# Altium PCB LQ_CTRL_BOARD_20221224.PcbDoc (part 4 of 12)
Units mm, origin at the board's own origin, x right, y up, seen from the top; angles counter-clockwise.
Board outline 260 x 142 mm, 6 copper layers (Top Layer, Mid-Layer 1, Mid-Layer 2, Mid-Layer 3, Mid-Layer 4, Bottom Layer); 1105 components, 1039 nets, 3898 pads, 1277 vias.
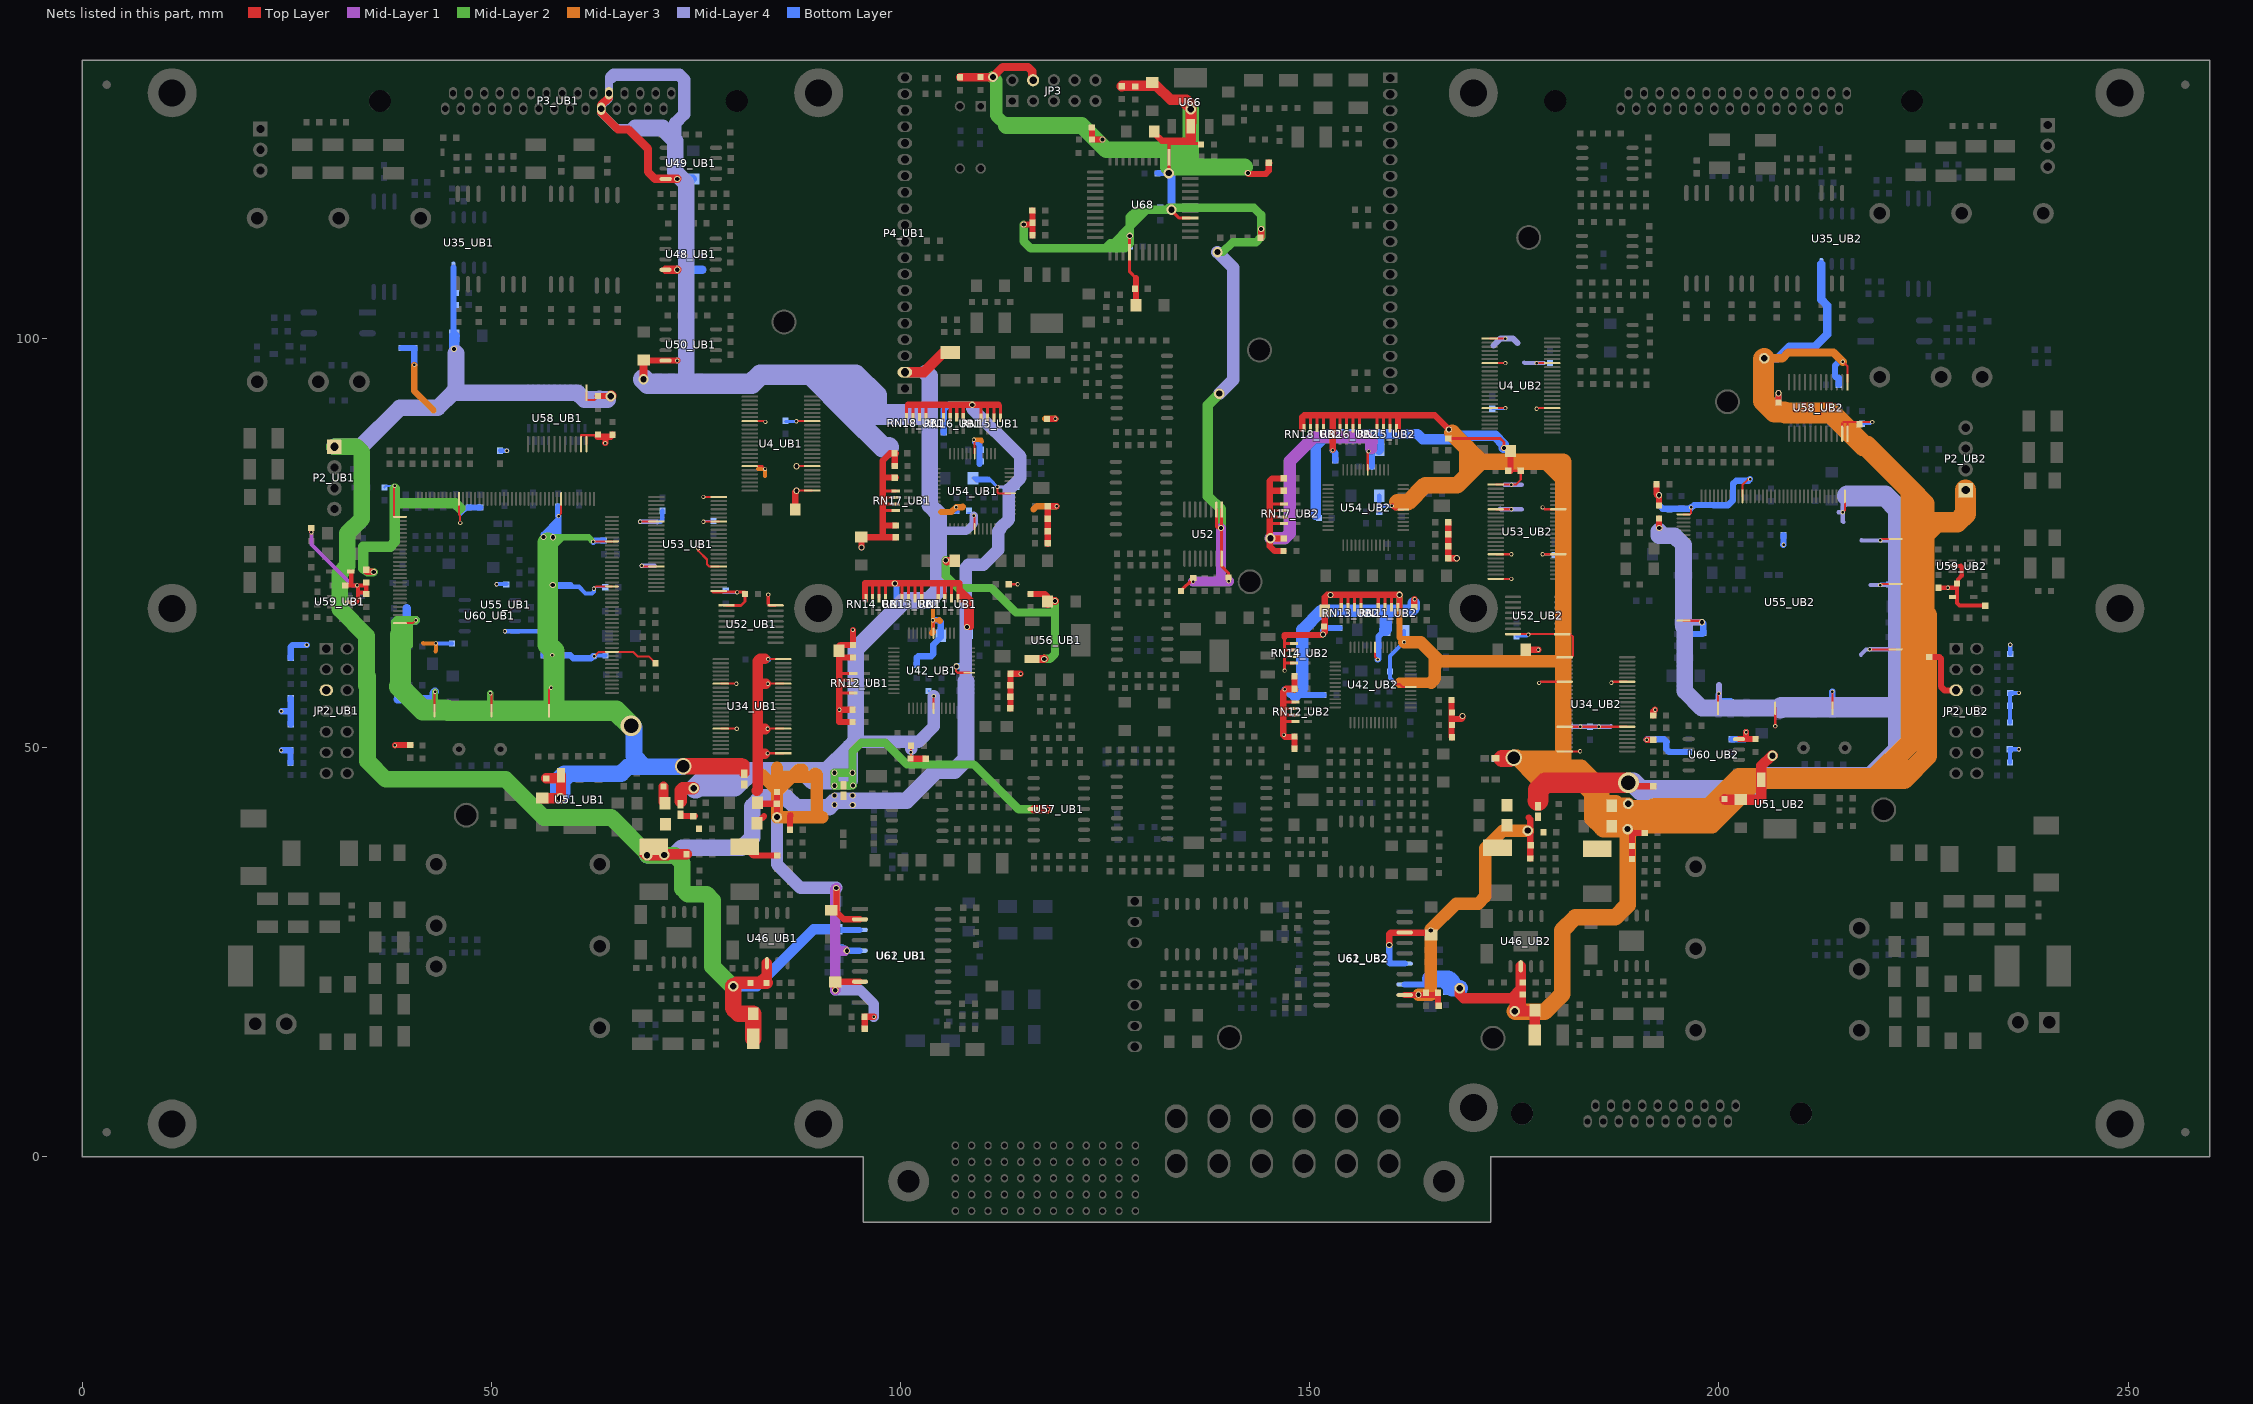
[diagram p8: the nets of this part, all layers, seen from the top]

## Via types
v1: diameter 0.508, hole 0.305, Top Layer to Bottom Layer, 845 vias
v2: diameter 0.762, hole 0.508, Top Layer to Bottom Layer, 317 vias
v3: diameter 1.27, hole 0.762, Top Layer to Bottom Layer, 77 vias
v4: diameter 2.032, hole 1.524, Top Layer to Bottom Layer, 15 vias
v5: diameter 2.032, hole 1.27, Top Layer to Bottom Layer, 11 vias
v6: diameter 1.27, hole 0.711, Top Layer to Bottom Layer, 8 vias
v7: diameter 2.54, hole 1.778, Top Layer to Bottom Layer, 3 vias
v8: diameter 1.524, hole 1.016, Top Layer to Bottom Layer, 1 vias

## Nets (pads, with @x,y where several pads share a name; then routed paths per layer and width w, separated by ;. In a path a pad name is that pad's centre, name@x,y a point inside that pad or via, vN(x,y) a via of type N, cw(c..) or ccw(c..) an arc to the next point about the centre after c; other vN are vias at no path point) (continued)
+3.3V_UB1: C291_UB1.1 C292_UB1.1 C293_UB1.1 C309_UB1.1 C315_UB1.1 C316_UB1.1 C317_UB1.1 C318_UB1.1 C323_UB1.2 C383_UB1.1 C385_UB1.1 C386_UB1.1 C387_UB1.1 C388_UB1.1 C391_UB1.2 C413_UB1.1 C414_UB1.1 C417_UB1.1 C418_UB1.1 C419_UB1.1 D23_UB1.1 L4_UB1.1 R230_UB1.2 R244_UB1.1 R259_UB1.1 R261_UB1.2 R269_UB1.2 R278_UB1.2 R279_UB1.2 R280_UB1.2 R281_UB1.2 R284_UB1.2 R287_UB1.2 R290_UB1.2 R293_UB1.2 R308_UB1.1 R313_UB1.2 R314_UB1.2 R318_UB1.2 R320_UB1.2 R321_UB1.2 R323_UB1.2 R324_UB1.2 R326_UB1.2 R327_UB1.2 R329_UB1.2 RN12_UB1.2 RN12_UB1.4 RN12_UB1.6 RN12_UB1.8 RN17_UB1.2 RN17_UB1.4 RN17_UB1.6 RN17_UB1.8 U4_UB1.1 U4_UB1.7 U4_UB1.18 U4_UB1.31 U4_UB1.42 U34_UB1.1 U34_UB1.7 U34_UB1.18 U34_UB1.24 U34_UB1.31 U34_UB1.42 U42_UB1.18 U52_UB1.1 U52_UB1.16 U53_UB1.1 U53_UB1.7 U53_UB1.18 U53_UB1.24 U53_UB1.31 U53_UB1.42 U54_UB1.18 U61_UB1.6 U62_UB1.2 U62_UB1.8 | length 262.3
  Top Layer w0.254: v1@68.123,77.622 U53_UB1.31@70.028,77.622 ; v1@68.377,72.111 68.38,72.113 U53_UB1.42@70.18,72.113 ; v1(75.286,74.346) 75.286,74.041 76.352,72.974 76.352,72.415 76.654,72.113 U53_UB1.7@77.8,72.113 ; v1(75.921,77.597) 75.937,77.613 U53_UB1.18@77.8,77.613 ; v1@75.921,80.613 U53_UB1.24@77.8,80.613 ; U34_UB1.42@78.054,52.301 v1(79.985,52.301) ; U34_UB1.31@78.054,57.801 79.943,57.801 v1(79.959,57.785) ; U4_UB1.42@81.585,84.382 83.131,84.382 v1(83.464,84.049) ; U4_UB1.31@81.585,89.882 v1@83.49,89.882 ; v1(83.769,49.276) 83.795,49.301 U34_UB1.1@85.674,49.301 ; v1(83.769,52.301) U34_UB1.7@85.674,52.301 ; v1(83.795,57.801) U34_UB1.18@85.674,57.801 ; v1(83.82,60.801) U34_UB1.24@85.674,60.801 ; v1(87.274,89.865) 87.291,89.882 U4_UB1.18@89.205,89.882 ; v2@87.293,81.381 v2(87.3,81.381) ; v2@87.293,81.382 U4_UB1.1@89.205,81.382 ; v2(87.3,84.379) 87.303,84.382 U4_UB1.7@89.205,84.382 ; v1(103.962,65.546) 104.049,65.459 U42_UB1.18@104.049,63.985 ; v1(108.966,87.605) 109.063,87.507 U54_UB1.18@109.063,85.91 ; R293_UB1.2@113.222,69.952 v1(114.3,69.952)
  Top Layer w0.381: U53_UB1.1@77.089,68.986 81.001,68.986 81.001,67.843 80.518,67.361 U52_UB1.1@78.74,67.361 ; v1(83.845,68.682) 83.845,67.539 84.023,67.361 U52_UB1.16@84.74,67.361 ; 92.532,55.626 92.564,55.594 ; 92.532,56.337 92.589,56.394 ; 92.532,57.226 92.564,57.194 ; 92.532,57.996 92.533,57.995 ; 92.558,58.268 RN12_UB1.6@94.247,58.268 ; 92.575,57.461 RN12_UB1.4@94.234,57.461 ; 92.575,59.061 RN12_UB1.8@94.234,59.061 ; 92.6,56.661 RN12_UB1.2@94.234,56.661 ; 97.841,79.019 97.898,78.962 RN17_UB1.2@99.441,78.962 ; 97.841,79.781 97.86,79.762 RN17_UB1.4@99.441,79.762 ; 97.841,80.493 97.911,80.562 RN17_UB1.6@99.441,80.562 ; 97.841,81.318 97.885,81.363 RN17_UB1.8@99.441,81.363
  Top Layer w0.762: L4_UB1.1@80.975,37.871 82.042,36.805 R269_UB1.2@84.938,36.805 ; C291_UB1.1@83.109,41.377 83.337,41.605 ; C292_UB1.1@83.185,43.104 83.21,43.129 C317_UB1.1@84.887,43.129 ; v3@84.836,41.478 84.912,41.554 D23_UB1.1@84.912,44.577 ; C293_UB1.1@86.487,39.954 86.487,41.656 86.563,41.732 ; C383_UB1.1@87.147,79.087 87.147,81.236 v2@87.293,81.381 ; v2(92.024,20.345) C417_UB1.1@92.024,21.361 92.05,21.387 U62_UB1.8@95.052,21.387 ; v2@92.177,32.741 92.177,29.921 93.091,29.007 U62_UB1.2@95.052,29.007 ; 92.532,53.111 92.532,55.626 92.532,56.337 92.532,57.226 92.532,57.996 92.532,60.935 ; v1(92.543,54.61) R281_UB1.2@94.132,54.61 ; 92.645,53.111 R280_UB1.2@94.132,53.111 ; v1(94.183,64.364) 94.209,64.338 94.209,64.313 94.198,64.302 R279_UB1.2@94.198,62.535 92.659,62.535 92.532,62.408 92.532,60.935 ; R278_UB1.2@94.198,61.011 92.608,61.011 92.532,60.935 ; v2(95.225,74.447) C385_UB1.1@95.225,75.743 95.275,75.692 97.841,75.692 ; C418_UB1.1@95.631,15.646 95.631,17.069 C419_UB1.1@95.606,17.094 v1(96.749,17.094) ; R320_UB1.2@99.289,84.404 99.289,85.827 C318_UB1.1@99.416,85.954 ; R321_UB1.2@99.416,75.692 97.841,75.692 ; R323_UB1.2@99.416,77.14 97.853,77.14 97.841,77.152 ; R318_UB1.2@99.441,82.982 97.866,82.982 97.841,83.007 ; C318_UB1.1@99.441,85.928 C318_UB1.1@99.416,85.954 ; R284_UB1.2@113.426,54.813 113.436,54.824 R244_UB1.1@113.436,59.004 v1(114.681,59.004) ; R329_UB1.2@117.907,90.145 118.923,90.145 v1(118.923,90.17) ; R324_UB1.2@118.008,74.91 R326_UB1.2@118.008,76.434 R327_UB1.2@118.008,77.958 R308_UB1.1@118.008,79.477 v1(119.075,79.477) ; 97.841,75.692 97.841,77.152 ; 97.841,77.152 97.841,79.019 97.841,79.781 97.841,80.493 97.841,81.318 97.841,83.007 ; 97.841,83.007 97.841,85.065 98.73,85.954 C318_UB1.1@99.416,85.954
  Top Layer w1.27: 82.448,44.729 82.55,44.831 82.55,49.276 ; 83.439,49.225 82.601,49.225 82.55,49.276 ; 83.439,52.273 83.464,52.248 82.626,52.248 82.55,52.324 ; 83.439,60.858 82.829,60.858 82.55,60.579 82.55,57.81 ; 83.515,57.801 82.559,57.801 82.55,57.81 ; 82.55,49.276 82.55,52.324 ; 82.55,52.324 82.55,57.81
  Mid-Layer 1 w1.27: v2(92.024,20.345) 92.024,32.715 v2(92.151,32.842) ; 92.024,25.044 92.151,25.171 v2@93.193,25.171
  Mid-Layer 2 w0.254: v1(68.174,77.597) v1@68.224,77.648
  Mid-Layer 3 w0.508: 82.575,84.049 v1(83.464,84.049) 83.464,83.185 ; 103.962,64.135 v1(103.962,65.546) ; 103.962,66.878 v1(103.962,65.546) ; 104.736,65.546 v1(103.962,65.546) ; v1(108.966,87.605) 109.88,87.605 ; 109.931,87.376 109.957,87.401
  Mid-Layer 3 w0.762: 103.886,64.033 103.861,64.033 103.962,64.135 ; 104.736,65.546 104.826,65.456 ; 104.978,78.791 106.217,78.791 v1(106.801,79.374) 107.568,79.374 107.62,79.426 ; 116.256,79.121 116.611,79.477 v1(119.075,79.477) ; 117.704,90.17 v1(118.923,90.17)
  Mid-Layer 3 w1.524: 82.931,46.761 84.912,44.78 ; 84.912,47.523 84.912,46.406 ; 87.986,47.295 87.605,47.295 86.716,46.406 ; 90.418,41.455 90.37,41.504 89.535,41.504 ; 84.912,44.602 86.716,46.406 ; 84.912,44.602 84.912,44.78 ; 84.912,44.602 v3(84.912,41.504) 89.535,41.504 ; 84.912,44.78 84.912,46.406 ; 84.912,46.406 86.716,46.406 ; 86.716,46.406 89.205,46.406 89.611,46.812 89.764,46.66 89.764,41.732 89.535,41.504
  Mid-Layer 4 w0.508: v1(68.174,77.597) 70.216,77.597 70.282,77.531 ; v1(68.377,72.212) 69.952,72.212 70.002,72.161
  Mid-Layer 4 w1.27: v2(92.024,20.345) 95.072,20.345 96.749,18.669 v1(96.749,17.094)
  Mid-Layer 4 w1.524: v3(84.912,41.504) 84.912,35.712 87.782,32.842 v2(92.151,32.842)
  Bottom Layer w0.254: v1(68.174,77.597) v1@68.224,77.648 ; v1(75.921,77.597) 75.997,77.673 C387_UB1.1@77.165,77.673
  Bottom Layer w0.381: C316_UB1.1@78.664,69.164 78.664,69.012 78.715,68.961 v1(80.035,68.961) ; C386_UB1.1@85.954,89.84 87.249,89.84 v1(87.274,89.865)
  Bottom Layer w0.508: v1(68.174,77.597) 70.714,77.597 70.891,77.775 70.891,78.918 R313_UB1.2@70.917,78.943
  Bottom Layer w0.762: C388_UB1.1@82.652,60.757 83.775,60.757 v1(83.82,60.801) ; C414_UB1.1@92.685,25.578 92.735,25.527 92.964,25.527 93.32,25.171 U61_UB1.6@95.001,25.171 ; R261_UB1.2@101.981,60.071 101.981,60.985 102.159,61.163 103.759,61.163 104.013,61.417 104.013,62.56 104.927,63.475 C315_UB1.1@104.927,63.652 104.927,65.354 104.724,65.557 104.216,65.557 ; R314_UB1.2@106.858,78.918 v1@106.858,79.299 ; 109.093,87.376 109.322,87.376 109.652,87.046 C391_UB1.2@109.652,84.658
  other v1: 75.921,80.62 83.49,89.789
  other v2: 93.447,25.171
+3.3V_UB2: C291_UB2.1 C292_UB2.1 C293_UB2.1 C309_UB2.1 C315_UB2.1 C316_UB2.1 C317_UB2.1 C318_UB2.1 C323_UB2.2 C383_UB2.1 C385_UB2.1 C386_UB2.1 C387_UB2.1 C388_UB2.1 C391_UB2.2 C413_UB2.1 C414_UB2.1 C417_UB2.1 C418_UB2.1 C419_UB2.1 D23_UB2.1 L4_UB2.1 R230_UB2.2 R244_UB2.1 R259_UB2.1 R261_UB2.2 R269_UB2.2 R278_UB2.2 R279_UB2.2 R280_UB2.2 R281_UB2.2 R284_UB2.2 R287_UB2.2 R290_UB2.2 R293_UB2.2 R308_UB2.1 R313_UB2.2 R314_UB2.2 R318_UB2.2 R320_UB2.2 R321_UB2.2 R323_UB2.2 R324_UB2.2 R326_UB2.2 R327_UB2.2 R329_UB2.2 RN12_UB2.2 RN12_UB2.4 RN12_UB2.6 RN12_UB2.8 RN17_UB2.2 RN17_UB2.4 RN17_UB2.6 RN17_UB2.8 U4_UB2.1 U4_UB2.7 U4_UB2.18 U4_UB2.31 U4_UB2.42 U34_UB2.1 U34_UB2.7 U34_UB2.18 U34_UB2.24 U34_UB2.31 U34_UB2.42 U42_UB2.18 U52_UB2.1 U52_UB2.16 U53_UB2.1 U53_UB2.7 U53_UB2.18 U53_UB2.24 U53_UB2.31 U53_UB2.42 U54_UB2.18 U61_UB2.6 U62_UB2.2 U62_UB2.8 | length 299.5
  Top Layer w0.254: U54_UB2.18@157.092,83.923 157.092,85.997 157.302,86.207 157.226,86.207 v1(157.201,86.182) ; U42_UB2.18@157.984,62.25 157.984,61.091 v1(158.318,60.757) ; U4_UB2.18@172.009,91.474 v1(173.914,91.474) ; U4_UB2.7@172.009,96.974 173.911,96.974 v1(173.914,96.977) ; U4_UB2.1@172.009,99.974 v1(173.914,99.974) ; U53_UB2.24@172.745,70.618 v1@174.644,70.618 ; U53_UB2.18@172.745,73.618 174.641,73.618 v1(174.65,73.609) ; U53_UB2.7@172.745,79.118 174.648,79.118 v1(174.65,79.121) ; U53_UB2.1@172.745,82.118 v1(174.65,82.118) 175.184,82.118 175.793,82.728 R313_UB2.2@175.793,83.82 174.523,83.82 C318_UB2.1@174.269,83.82 ; v1(174.65,70.612) v1@174.644,70.618 ; v1@174.65,70.618 v1@174.644,70.618 ; U52_UB2.16@174.848,63.856 U52_UB2.1@180.848,63.856 181.839,63.856 182.194,63.5 182.194,61.239 181.991,61.036 U34_UB2.1@181.178,61.036 ; v1@177.724,91.474 U4_UB2.31@179.629,91.474 ; v1(177.724,96.977) 177.727,96.974 U4_UB2.42@179.629,96.974 ; v1(178.029,57.887) 178.178,58.036 U34_UB2.7@181.178,58.036 ; v1(178.46,73.613) 178.465,73.618 U53_UB2.31@180.365,73.618 ; v1(178.46,79.35) 178.692,79.118 U53_UB2.42@180.365,79.118 ; U34_UB2.24@181.178,49.536 183.013,49.536 v1(183.032,49.555) ; U34_UB2.18@181.178,52.536 v1(183.083,52.536) v1(185.344,52.536) U34_UB2.31@188.798,52.536 ; v1(186.868,57.912) 186.868,57.861 187.043,58.036 U34_UB2.42@188.798,58.036
  Top Layer w0.381: 145.11,77.317 145.155,77.362 RN17_UB2.2@146.852,77.362 ; 145.11,78.384 145.332,78.162 RN17_UB2.4@146.852,78.162 ; 145.11,78.994 145.142,78.962 RN17_UB2.6@146.852,78.962 ; 145.11,79.73 145.142,79.762 RN17_UB2.8@146.852,79.762 ; 146.761,53.213 146.793,53.181 RN12_UB2.2@148.26,53.181 ; 146.761,54.102 146.882,53.981 RN12_UB2.4@148.26,53.981 ; 146.761,54.737 146.806,54.781 RN12_UB2.6@148.26,54.781 ; 146.761,55.575 146.768,55.582 RN12_UB2.8@148.26,55.582 ; R329_UB2.2@166.929,87.757 173.304,87.757 173.736,87.325 v2(173.736,86.614)
  Top Layer w0.762: R321_UB2.2@146.801,74.02 145.69,74.02 145.11,74.599 v3@145.11,75.59 ; R323_UB2.2@146.827,75.539 145.161,75.539 v3@145.11,75.59 ; R318_UB2.2@146.827,81.381 145.237,81.381 145.11,81.508 ; R320_UB2.2@146.827,82.905 146.801,82.88 145.415,82.88 145.11,82.575 145.11,81.508 ; R279_UB2.2@148.133,58.699 R278_UB2.2@148.133,57.175 147.117,57.175 146.761,56.82 146.761,55.575 146.761,54.737 146.761,54.102 146.761,53.213 146.761,51.537 147.015,51.283 148.082,51.283 R281_UB2.2@148.158,51.359 R280_UB2.2@148.158,49.86 ; v2(159.715,25.883) 159.715,27.229 159.868,27.381 U62_UB2.8@161.615,27.381 164.53,27.381 C417_UB2.1@164.835,27.076 ; U62_UB2.2@161.615,19.761 165.393,19.761 C419_UB2.1@165.673,20.041 165.673,18.542 C414_UB2.1@165.774,18.44 ; R293_UB2.2@162.789,67.183 162.789,68.097 v1(162.814,68.123) ; R308_UB2.1@166.929,77.52 R327_UB2.2@166.929,76.073 R326_UB2.2@166.929,74.599 R324_UB2.2@166.929,73.126 v2(167.97,73.127) ; R244_UB2.1@167.335,55.796 167.335,53.492 ; R284_UB2.2@167.386,51.253 167.335,51.304 167.335,53.492 ; v2@168.656,53.797 168.656,53.619 168.529,53.492 167.335,53.492 ; v2@173.711,86.589 v2(173.736,86.614) 174.32,86.614 174.32,86.462 C309_UB2.1@174.549,86.233 174.549,83.845 C318_UB2.1@174.523,83.82 ; C383_UB2.1@176.403,61.951 v1(177.952,61.951) ; 176.759,41.453 176.962,41.25 C293_UB2.1@176.962,36.449 ; v3@145.11,75.59 145.11,77.317 145.11,78.384 145.11,78.994 145.11,79.73 145.11,81.508
  Mid-Layer 1 w1.524: v3(145.212,75.565) 146.939,75.565 147.549,76.175 147.549,84.963 150.495,87.909 157.023,87.909 157.556,87.376 157.531,87.351 157.531,86.538
  Mid-Layer 3 w0.254: v1(177.724,96.977) 178.867,96.977 178.892,96.952
  Mid-Layer 3 w0.762: v1@147.066,57.099 148.107,57.099 ; 148.158,57.048 148.107,57.099 ; 148.234,57.099 148.107,57.099
  Mid-Layer 3 w1.524: v2(163.297,19.787) 163.322,19.812 164.795,19.812 ; 164.821,19.787 164.795,19.812 ; v3(176.657,39.853) 173.609,39.853 171.45,37.694 171.45,31.775 170.612,30.937 167.919,30.937 164.795,27.813 v2(164.795,27.635) 164.795,19.812
  Mid-Layer 4 w0.508: 173.279,79.197 173.355,79.121 v1(174.65,79.121) 175.87,79.121 175.92,79.07 ; 173.787,82.093 173.812,82.118 v1(174.65,82.118) 175.92,82.118 ; 176.225,97.028 176.276,96.977 v1(177.724,96.977) 178.613,96.977 ; 181.585,52.476 181.644,52.536 v1(183.083,52.536) v1(185.344,52.536) 186.75,52.536 186.817,52.603
  Mid-Layer 4 w0.762: 172.466,99.136 173.304,99.974 v1(173.914,99.974) 174.854,99.974 175.387,99.441
  Bottom Layer w0.254: C387_UB2.1@172.314,91.389 173.829,91.389 v1(173.914,91.474) ; R230_UB2.2@175.285,63.602 176.53,63.602 v1(176.733,63.805) ; v1(177.724,96.977) C316_UB2.1@179.375,96.977 ; v1(178.46,73.613) 179.853,73.613 C388_UB2.1@179.934,73.533 ; C386_UB2.1@181.813,52.578 C386_UB2.1@181.855,52.536
  Bottom Layer w0.508: C386_UB2.1@181.855,52.536 v1(183.083,52.536) v1(185.344,52.536)
  Bottom Layer w0.762: 149.098,57.277 148.92,57.099 v1(146.939,57.099) 147.625,56.413 148.234,56.413 R261_UB2.2@151.689,56.413 ; C391_UB2.2@157.607,84.353 157.607,86.182 157.556,86.233 157.709,86.385 C385_UB2.1@158.471,86.385 ; v1(158.318,60.757) 158.394,60.833 C317_UB2.1@158.394,62.459 158.394,63.551 C315_UB2.1@159.233,64.389 ; v2@159.715,25.832 159.715,23.724 159.842,23.597 U61_UB2.6@161.609,23.597
  Bottom Layer w1.27: 150.724,78.461 150.724,86.843 152.197,88.316 157.988,88.316 ; C385_UB2.1@158.471,86.385 158.471,87.833 157.988,88.316 ; 172.187,88.113 172.161,88.087 ; v2(173.736,86.614) 173.736,87.02 172.669,88.087 172.161,88.087 ; 157.988,88.316 163.144,88.316 163.805,87.655 167.51,87.655 167.942,88.087 172.161,88.087
  Bottom Layer w1.524: 148.234,56.413 148.92,57.099 ; 149.098,57.277 149.098,64.364 151.46,66.726 152.146,66.726 ; 151.689,66.269 152.146,66.726 ; C315_UB2.1@159.233,64.389 159.283,64.44 159.283,66.319 158.877,66.726 ; 162.738,67.615 162.738,67.056 162.408,66.726 158.877,66.726 ; 152.146,66.726 158.877,66.726
  other v1: 146.85,51.537 177.724,91.389
  other v2: 168.681,53.848
+3.3VD_UB1: C313_UB1.1 C320_UB1.1 C346_UB1.2 C347_UB1.2 C348_UB1.2 C349_UB1.2 C350_UB1.2 C351_UB1.2 C352_UB1.2 C353_UB1.2 C406_UB1.1 C408_UB1.2 D24_UB1.2 JP2_UB1.5 LED5_UB1.1 LED13_UB1.1 R15_UB1.1 R257_UB1.2 R258_UB1.2 R259_UB1.2 R277_UB1.1 R303_UB1.1 R306_UB1.1 R307_UB1.1 R309_UB1.1 R311_UB1.2 R312_UB1.1 R331_UB1.1 R336_UB1.1 R346_UB1.2 R352_UB1.1 R353_UB1.1 R358_UB1.2 R361_UB1.2 R362_UB1.2 R363_UB1.2 U51_UB1.3 U55_UB1.9 U55_UB1.71 U55_UB1.93 U55_UB1.107 U55_UB1.121 U55_UB1.143 U55_UB1.159 U55_UB1.170 U58_UB1.23 U58_UB1.24 U59_UB1.5 U60_UB1.8 | length 243.6
  Top Layer w0.254: U55_UB1.71@38.84,65.191 40.426,65.191 v1(40.792,65.557) ; U55_UB1.93@43.04,54.491 43.04,56.553 43.129,56.642 v1(43.129,56.82) ; v1(49.886,56.642) 49.886,56.691 50.04,56.536 U55_UB1.107@50.04,54.491 ; U55_UB1.121@57.04,54.491 57.04,55.982 ; v1(57.302,57.302) 57.048,57.048 57.048,56.312 ; v1(58.217,78.283) 58.54,78.606 U55_UB1.9@58.54,80.391 ; U58_UB1.23@60.976,87.07 60.976,88.154 62.849,88.154 R352_UB1.1@62.885,88.118 ; U58_UB1.24@61.626,87.07 61.626,88.118 R352_UB1.1@62.885,88.118 ; v1(62.459,75.159) 62.491,75.191 U55_UB1.170@64.74,75.191 ; v1(62.535,69.405) 62.821,69.691 U55_UB1.159@64.74,69.691 ; v1(62.611,61.163) 63.139,61.691 U55_UB1.143@64.74,61.691 67.316,61.691 67.869,61.138 69.239,61.138 R331_UB1.1@70.077,60.3 ; R352_UB1.1@63.017,87.986 R352_UB1.1@62.885,88.118 ; 57.04,55.982 57.04,56.304 57.048,56.312 ; 57.04,55.982 57.048,55.99 57.048,56.312
  Top Layer w0.508: LED5_UB1.1@27.991,76.81 27.991,76.327 v1(28.016,76.302) ; R353_UB1.1@32.163,69.787 33.617,69.787 33.731,69.672 33.731,69.051 ; U59_UB1.5@32.62,67.803 33.564,67.803 33.731,67.97 33.731,69.051 ; 32.893,69.875 D24_UB1.2@32.893,71.526 ; v1(33.61,69.799) 34.366,69.799 R277_UB1.1@34.722,70.155 R346_UB1.2@34.722,68.961 ; R346_UB1.2@34.722,68.758 R346_UB1.2@34.722,68.961 ; 33.731,69.051 33.821,68.961 R346_UB1.2@34.722,68.961
  Top Layer w0.762: v1(38.227,50.267) 38.278,50.317 LED13_UB1.1@40.107,50.317 ; R352_UB1.1@62.992,87.96 63.017,87.986 63.957,87.986 ; v1(63.932,87.198) 63.957,87.224 63.957,87.986 ; C406_UB1.1@64.821,88.214 64.592,87.986 63.957,87.986
  Top Layer w1.27: C313_UB1.1@56.21,43.815 v3(58.42,43.815) 58.522,43.917 U51_UB1.3@58.522,46.609 58.141,46.228 C320_UB1.1@56.718,46.228 ; R259_UB1.2@80.899,46.939 80.899,47.981
  Top Layer w2.032: v4(73.457,47.701) 80.518,47.701
  Mid-Layer 1 w0.508: v1(28.016,76.302) 28.016,74.828 33.045,69.799 v1(33.61,69.799)
  Mid-Layer 2 w0.762: 38.278,64.668 39.751,64.668 ; v1(43.129,56.82) 43.129,54.762 43.307,54.585 ; 49.835,54.483 49.886,54.534 v1(49.886,56.642) ; 56.896,73.304 56.896,73.838 58.75,75.692 ; v2(57.531,75.692) 58.75,75.692 ; 62.255,75.336 61.9,75.692 58.75,75.692
  Mid-Layer 2 w1.016: 38.913,61.519 39.903,62.509 39.903,65.557 ; 38.913,63.779 38.278,64.414 38.278,64.668 38.278,65.38 38.456,65.557 39.903,65.557 ; v1(40.792,65.557) 39.903,65.557
  Mid-Layer 2 w2.54: 38.76,57.455 41.631,54.585 43.307,54.585 44.607,54.585 44.708,54.483 49.835,54.483 57.658,54.483 ; 38.913,57.556 38.913,61.519 38.913,63.779 ; 56.896,73.304 56.896,62.56 57.658,61.798 57.658,54.483 ; 56.896,73.838 56.896,75.006 ; v7(67.081,52.654) 65.253,54.483 57.658,54.483
  Mid-Layer 3 w0.508: 41.681,62.763 41.732,62.713 v1(43.231,62.713) 43.231,61.824 43.18,61.773
  Mid-Layer 3 w0.762: v1(40.6,96.749) 40.6,93.563 42.951,91.211
  Bottom Layer w0.254: v1(62.535,69.405) 62.726,69.596 C351_UB1.2@64.008,69.596
  Bottom Layer w0.508: v1(43.231,62.713) R362_UB1.2@45.187,62.713 ; C347_UB1.2@49.886,55.372 v1(49.886,56.642) ; v1(50.648,69.952) 50.698,70.002 R361_UB1.2@51.841,70.002 ; R336_UB1.1@51.054,86.258 v1@51.968,86.258 ; v1(51.664,64.211) U60_UB1.8@52.908,64.211 56.21,64.211 56.413,64.414 R358_UB1.2@56.413,65.659 ; v2(57.506,69.875) 57.734,69.647 60.706,69.647 61.519,68.834 62.306,68.834 62.535,69.063 v1(62.535,69.405) ; v1(62.611,61.163) 62.687,61.239 C350_UB1.2@63.957,61.239
  Bottom Layer w0.762: v1@24.384,54.432 R307_UB1.1@25.502,54.432 ; v1@24.435,49.657 R312_UB1.1@25.476,49.657 R311_UB1.2@25.476,48.108 ; R309_UB1.1@25.502,52.857 R307_UB1.1@25.502,54.432 ; R306_UB1.1@25.502,56.032 R307_UB1.1@25.502,54.432 ; R303_UB1.1@25.502,60.935 25.502,62.281 25.756,62.535 v1(27.457,62.535) ; R258_UB1.2@39.065,98.831 R257_UB1.2@40.595,98.831 40.595,96.754 v1(40.6,96.749) ; R363_UB1.2@56.388,61.29 v1(57.455,61.29) 59.639,61.29 60.02,60.909 62.188,60.909 62.442,61.163 v1(62.611,61.163) ; v2(57.506,69.875) 59.639,69.875 59.665,69.85 ; C353_UB1.2@58.166,79.426 58.166,78.334 v1(58.217,78.283) 58.217,77.826 ; v1(62.459,75.159) 62.611,75.311 C352_UB1.2@63.729,75.311 ; 57.023,75.692 56.413,75.692 v2(56.388,75.717) 56.388,75.997 58.217,77.826 ; 57.023,75.692 v2(57.531,75.692) 58.115,75.692 58.217,75.794 58.217,76.886 ; 57.023,75.692 58.217,76.886 ; 58.217,76.886 58.217,77.826
  Bottom Layer w1.016: R15_UB1.1@38.532,55.905 41.427,55.905 41.453,55.931 42.951,55.931 42.951,56.642 v1(43.129,56.82) ; C408_UB1.2@39.675,67.031 39.675,65.583 C349_UB1.2@39.649,65.557 v1(40.792,65.557)
  Bottom Layer w2.032: 58.979,46.558 59.233,46.812 65.862,46.812 66.7,47.65 68.732,47.65 ; v7@67.437,52.451 67.437,48.946 68.732,47.65 ; v4(73.457,47.701) 73.406,47.65 68.732,47.65
  Bottom Layer w2.54: v3@58.42,44.399 58.42,45.999 58.979,46.558
  other v1: 24.308,49.657 24.333,54.432 51.892,86.258
+3.3VD_UB2: C313_UB2.1 C320_UB2.1 C346_UB2.2 C347_UB2.2 C348_UB2.2 C349_UB2.2 C350_UB2.2 C351_UB2.2 C352_UB2.2 C353_UB2.2 C406_UB2.1 C408_UB2.2 D24_UB2.2 JP2_UB2.5 LED5_UB2.1 LED13_UB2.1 R15_UB2.1 R257_UB2.2 R258_UB2.2 R259_UB2.2 R277_UB2.1 R303_UB2.1 R306_UB2.1 R307_UB2.1 R309_UB2.1 R311_UB2.2 R312_UB2.1 R331_UB2.1 R336_UB2.1 R346_UB2.2 R352_UB2.1 R353_UB2.1 R358_UB2.2 R361_UB2.2 R362_UB2.2 R363_UB2.2 U51_UB2.3 U55_UB2.9 U55_UB2.71 U55_UB2.93 U55_UB2.107 U55_UB2.121 U55_UB2.143 U55_UB2.159 U55_UB2.170 U58_UB2.23 U58_UB2.24 U59_UB2.5 U60_UB2.8 | length 255.9
  Top Layer w0.254: U55_UB2.71@195.685,65.496 197.474,65.496 197.485,65.507 v2@197.79,65.507 ; U55_UB2.93@199.885,54.796 199.885,56.477 v1(200,56.591) ; v1(206.883,52.629) 206.883,52.479 206.885,52.476 U55_UB2.107@206.885,54.796 ; v1(213.868,56.845) 213.885,56.828 U55_UB2.121@213.885,54.796 ; U58_UB2.23@215.069,88.34 215.069,89.593 215.24,89.764 215.798,89.764 ; v1(215.138,78.74) 215.385,78.987 U55_UB2.9@215.385,80.696 ; U58_UB2.24@215.719,88.34 215.719,89.685 215.798,89.764 ; v1(218.44,61.996) U55_UB2.143@221.585,61.996 ; v1(218.745,89.764) 215.798,89.764 ; v1(219.71,69.85) 219.856,69.996 U55_UB2.159@221.585,69.996 ; v1(219.735,75.311) 219.92,75.496 U55_UB2.170@221.585,75.496
  Top Layer w0.508: R346_UB2.2@226.822,69.52 v1(227.99,69.52) ; v1@228.016,69.52 v1(227.99,69.52) ; D24_UB2.2@228.54,68.402 228.88,68.402 229.108,68.631 ; U59_UB2.5@228.595,72.176 229.555,72.176 229.591,72.212 229.667,72.136 229.667,70.993 229.21,70.536 229.21,70.129 R353_UB2.1@229.108,70.028 229.108,69.52 ; LED5_UB2.1@232.537,67.335 229.413,67.335 229.108,67.64 229.108,68.631 ; v1(227.99,69.52) 229.108,69.52 ; 229.108,68.631 229.108,69.52
  Top Layer w0.762: v7(188.951,45.695) 189.382,45.263 R361_UB2.2@191.973,45.263 ; v1(191.186,50.952) R363_UB2.2@191.989,50.952 ; LED13_UB2.1@191.973,53.899 191.973,54.392 v1(192.197,54.615) ; R277_UB2.1@192.684,77.996 192.684,76.835 v2(192.71,76.81) ; U60_UB2.8@202.459,51.029 203.327,51.029 ; v1(203.327,51.867) 203.327,51.029 ; R358_UB2.2@204.343,51.029 203.327,51.029 ; R258_UB2.2@207.289,92.151 v2(207.289,93.294) ; R331_UB2.1@225.704,61.062 226.924,61.062 227.127,60.858 227.127,57.455 227.609,56.972 228.956,56.972 JP2_UB2.5@228.981,56.998
  Top Layer w1.27: 177.902,43.383 177.902,43.536 177.902,44.78 177.927,44.806 ; C320_UB2.1@200.685,43.713 200.762,43.637 C313_UB2.1@202.692,43.637 204.902,43.637 205.181,43.917 U51_UB2.3@205.181,46.05 205.181,47.752 206.451,49.022 v3@206.578,49.022
  Top Layer w2.54: 177.902,43.536 177.927,43.561 177.927,44.806 178.816,45.695 v7(188.951,45.695)
  Mid-Layer 4 w0.508: 214.62,78.74 v1(215.138,78.74) ; 215.214,77.546 215.138,77.622 v1(215.138,78.74) ; 215.697,80.721 215.138,80.162 v1(215.138,78.74) ; 217.348,61.341 217.348,61.366 217.977,61.996 v1(218.44,61.996) 218.446,62.001 221.945,62.001 ; 217.424,75.336 217.449,75.311 v1(219.735,75.311) 221.894,75.311 221.945,75.26 ; 218.542,69.85 v1(219.71,69.85) 221.92,69.85 221.945,69.875
  Mid-Layer 4 w0.762: 195.834,64.643 196.494,65.303 v2(197.942,65.303) ; 200,57.633 v1(200,56.591) 200,54.864 200.025,54.839 ; v2(207.289,93.294) 207.289,91.897 207.416,91.77
  Mid-Layer 4 w2.032: 192.684,76.429 192.684,75.87 194.589,75.87 195.682,74.778 195.682,64.795 195.834,64.643 195.834,56.896 197.891,54.839 200.025,54.839 207.543,54.839
  Mid-Layer 4 w2.54: v7(188.951,45.695) 189.535,45.695 190.449,44.78 203.911,44.78 205.486,46.355 218.567,46.355 221.945,49.733 221.945,55.016 ; 207.543,54.839 207.62,54.915 221.844,54.915 221.945,55.016 ; 215.697,80.721 220.32,80.721 221.945,79.096 221.945,75.26 221.945,69.875 221.945,62.001 221.945,55.016
  Bottom Layer w0.254: R257_UB2.2@217.5,89.56 218.542,89.56 v1(218.745,89.764)
  Bottom Layer w0.508: v1(215.138,78.74) 215.138,79.321 C406_UB2.1@215.777,79.959 ; v1(219.71,69.85) 219.786,69.926 C349_UB2.2@220.802,69.926 ; v1(219.735,75.311) 220.726,75.311 C348_UB2.2@221.082,75.667 221.056,75.692 C346_UB2.2@221.056,77.14 ; R309_UB2.1@235.56,53.072 R307_UB2.1@235.56,55.118 235.56,56.617 R306_UB2.1@235.61,56.667 v1(236.652,56.667) ; R311_UB2.2@235.585,48.17 235.585,49.733 R312_UB2.1@235.534,49.784 235.548,49.798 v1(236.652,49.798) ; R303_UB2.1@235.59,61.443 235.61,61.463 v1(235.61,62.56)
  Bottom Layer w0.762: v1(191.186,50.952) 191.237,51.003 193.294,51.003 193.624,50.673 193.573,50.622 193.573,49.784 193.904,49.454 R362_UB2.2@196.312,49.454 ; C353_UB2.2@196.469,63.881 197.968,63.881 R15_UB2.1@198.095,64.008 198.095,65.151 v2(197.942,65.303) C352_UB2.2@196.469,65.303 ; v1@200,56.54 199.949,56.49 C351_UB2.2@199.949,55.575 200.025,55.651 C347_UB2.2@201.447,55.651 ; C408_UB2.2@201.574,51.003 203.175,51.003 203.327,51.156 v1(203.327,51.867) ; v1@207.874,74.778 207.899,74.803 R336_UB2.1@207.899,75.946 ; C350_UB2.2@213.843,55.575 213.843,56.82 v1(213.868,56.845)
  other v1: 207.901,74.778
  other v3: 206.553,48.997
+3V3A_UB1: C343_UB1.2 C344_UB1.2 C345_UB1.2 R277_UB1.2 U55_UB1.34 U55_UB1.45 | length 38.4
  Top Layer w0.254: R277_UB1.2@34.722,71.501 R277_UB1.2@34.722,71.73 ; v1(38.176,81.966) 38.125,81.915 38.125,78.257 38.192,78.191 U55_UB1.45@38.84,78.191 ; U55_UB1.34@46.04,80.391 46.04,78.461 46.203,78.298 v1(46.203,77.445)
  Top Layer w0.762: R277_UB1.2@34.722,71.501 34.743,71.48 35.607,71.48 v2(35.636,71.45)
  Mid-Layer 2 w0.254: v1(46.203,77.445) 46.203,79.223
  Mid-Layer 2 w1.016: 34.519,71.755 34.874,71.399 35.585,71.399 v2(35.636,71.45)
  Mid-Layer 2 w1.27: 34.519,71.755 34.366,71.907 34.366,74.549 37.643,74.549 38.227,75.133 38.227,79.832 ; 38.202,81.61 38.227,81.585 38.227,79.832 ; 46.203,79.223 45.593,79.832 38.227,79.832
  Bottom Layer w0.254: C343_UB1.2@36.957,81.788 37.135,81.966 v1(38.176,81.966) ; v1(46.203,77.445) 46.203,78.308 C344_UB1.2@47.219,79.324
  Bottom Layer w0.762: C344_UB1.2@47.219,79.324 C345_UB1.2@48.666,79.324
+3V3A_UB2: C343_UB2.2 C344_UB2.2 C345_UB2.2 R277_UB2.2 U55_UB2.34 U55_UB2.45 | length 22.5
  Top Layer w0.254: U55_UB2.45@195.685,78.496 196.451,78.496 196.596,78.641 v1(196.596,79.35) ; U55_UB2.34@202.885,80.696 202.885,82.108 203.581,82.804 v1(203.81,82.804)
  Top Layer w0.762: C343_UB2.2@192.38,82.169 192.38,80.975 192.684,80.67 R277_UB2.2@192.684,79.571
  Bottom Layer w0.762: v2(192.684,80.823) 192.684,79.604 193.116,79.172 C344_UB2.2@195.428,79.172 v1@196.418,79.172 ; v1(196.596,79.35) v1@196.418,79.172 ; v1(203.81,82.804) 203.606,82.601 202.108,82.601 201.727,82.22 201.727,80.213 201.117,79.604 199.365,79.604 199.339,79.629 196.977,79.629 196.52,79.172 v1@196.418,79.172
+3V3MS: C437.1 C439.1 C449.2 C450.2 C451.2 C452.2 C453.2 C454.2 JP3.4 LED1.1 LED2.1 LED3.1 LED4.1 LED19.1 LED20.1 LED21.1 R5.2 R7.1 R9.1 R35.1 R36.1 R37.1 R38.1 U52.1 U52.2 U52.16 U66.2 U68.15 U68.26 U68.35 | length 244.4
  Top Layer w0.381: v2(128.016,112.522) 128,112.506 U68.15@128,110.52 128,108.122 128.778,107.343 ; v3(132.791,120.193) 132.8,120.201 U68.35@132.8,122.12 132.8,123.825 136.576,123.825 LED21.1@136.728,123.673 ; v3@133.147,115.595 134.022,114.72 U68.26@135.4,114.72 ; R5.2@134.264,69.139 R9.1@135.763,70.637 ; v1(135.763,70.282) R9.1@135.763,70.637 ; R9.1@135.763,70.714 R9.1@135.763,70.637 ; U52.2@138.593,79.087 138.593,77.028 138.786,76.835 v2@139.243,76.835 ; U52.1@139.243,79.087 v2@139.243,76.835 ; v1(140.106,70.307) 140.081,70.333 R7.1@140.081,70.764 140.081,71.313 139.243,72.151 U52.16@139.243,73.087 v2@139.243,76.835
  Top Layer w0.762: v2(115.062,113.894) R37.1@116.078,113.894 ; R38.1@116.103,115.621 116.129,115.595 R37.1@116.129,114.122 R35.1@116.129,112.598 ; R36.1@123.393,125.4 LED20.1@123.393,124.282 124.663,124.282 v2(124.689,124.308) ; C449.2@128.778,104.064 128.778,107.343 ; C452.2@131.013,125.273 131.013,125.07 131.953,124.13 135.306,124.13 135.458,124.282 ; v2(142.443,120.193) 142.545,120.091 144.628,120.091 145.009,120.472 LED1.1@145.009,121.463 LED1.1@145.059,121.412 ; LED2.1@144.069,112.37 v2(144.069,113.36)
  Top Layer w1.016: LED4.1@107.264,131.902 111.227,131.902 112.486,133.162 115.575,133.162 116.098,132.639 116.098,131.647 JP3.4@116.205,131.54
  Top Layer w1.27: LED19.1@127.045,130.81 127.122,130.886 131.275,130.886 133.003,129.159 134.29,129.159 ; C437.1@130.404,130.886 C437.1@130.759,131.242 ; 135.458,124.282 U66.2@135.458,125.908 v3@135.458,127.483 ; U66.2@135.509,126.34 v3@135.509,127.533 ; 134.29,129.159 v3(135.458,127.991) v3@135.458,127.483 ; 134.29,129.159 134.95,129.159 135.509,128.6 v3@135.509,127.533 ; v3@135.458,127.483 v3@135.509,127.533
  Mid-Layer 1 w1.27: v1(135.763,70.282) 138.887,70.282 ; v2(139.167,76.81) 139.167,70.561 138.887,70.282 ; v1(140.106,70.307) 140.081,70.282 138.887,70.282
  Mid-Layer 2 w1.016: v2(115.062,113.894) 115.062,111.853 115.917,110.998 125.019,110.998 ; v3(133.121,115.697) v3@132.512,115.697 ; v3(138.735,110.541) 139.37,110.541 140.564,111.735 143.434,111.735 144.069,112.37 v2(144.069,113.36) 144.069,115.087 143.205,115.951 132.766,115.951 v3@132.512,115.697 ; 125.019,110.998 125.628,111.608 126.035,111.608 ; 125.019,110.998 127.432,110.998 128.016,111.582 v2(128.016,112.522) ; 126.035,111.608 127.102,111.608 v2(128.016,112.522) ; 126.035,111.608 128.016,113.589 ; v2(128.016,112.522) 128.016,113.589 ; 128.016,113.589 128.016,113.665 ; 128.016,113.665 130.048,115.697 ; 128.016,113.665 128.016,114.833 128.88,115.697 130.048,115.697 ; 130.048,115.697 v3@132.512,115.697
  Mid-Layer 2 w1.27: v3(138.963,93.243) 137.566,91.846 137.566,80.696 139.167,79.096 v2(139.167,76.81)
  Mid-Layer 2 w1.524: v3(111.303,131.928) 111.684,131.547 111.684,127.254 112.928,126.009
  Mid-Layer 2 w2.032: 112.928,126.009 122.149,126.009 125.12,123.038 132.817,123.038 ; 135.458,121.336 135.458,123.165 ; v3(135.458,127.991) 135.458,123.165 ; 138.811,120.929 134.722,120.929 ; 142.062,120.904 142.037,120.929 134.722,120.929 ; 132.715,122.936 132.817,123.038 ; 132.715,122.936 132.715,120.929 134.722,120.929 ; 132.715,122.936 134.722,120.929 ; 132.817,123.038 135.331,123.038 135.458,123.165
  Mid-Layer 4 w1.524: v3(138.735,110.541) 140.665,108.61 140.665,94.945 v3(138.963,93.243)
  Bottom Layer w0.381: C454.2@128.016,111.227 v2(128.016,112.522) ; C453.2@131.75,116.002 132.817,116.002 v3(133.121,115.697)
  Bottom Layer w0.762: C451.2@131.445,120.193 v3(132.791,120.193)
  Bottom Layer w1.016: v3(132.791,120.193) 133.121,119.863 v3(133.121,115.697)
+5V_UB1: C17_UB1.1 C228_UB1.1 C237_UB1.2 C238_UB1.2 C254_UB1.1 C255_UB1.1 C258_UB1.1 C265_UB1.1 C266_UB1.2 C294_UB1.1 C295_UB1.2 C367_UB1.1 C368_UB1.2 C405_UB1.2 C415_UB1.1 C416_UB1.1 D21_UB1.1 L3_UB1.1 P2_UB1.1 R39_UB1.1 R40_UB1.1 R229_UB1.1 R239_UB1.2 R263_UB1.1 R283_UB1.2 RN11_UB1.1 RN11_UB1.3 RN11_UB1.5 RN11_UB1.7 RN13_UB1.1 RN13_UB1.3 RN13_UB1.5 RN13_UB1.7 RN14_UB1.1 RN14_UB1.3 RN14_UB1.5 RN14_UB1.7 RN15_UB1.1 RN15_UB1.3 RN15_UB1.5 RN15_UB1.7 RN16_UB1.1 RN16_UB1.3 RN16_UB1.5 RN16_UB1.7 RN18_UB1.1 RN18_UB1.3 RN18_UB1.5 RN18_UB1.7 U35_UB1.8 U42_UB1.6 U46_UB1.2 U54_UB1.6 U58_UB1.1 U61_UB1.8 | length 415.3
  Top Layer w0.254: U58_UB1.1@61.626,93.37 61.626,92.527 61.697,92.456 62.56,92.456 C405_UB1.2@63.043,92.939 ; v2@106.782,59.919 106.782,59.305 106.952,59.135 U42_UB1.6@108.399,59.135 ; v1@111.836,81.661 111.836,81.229 112.005,81.06 ; 111.899,81.06 112.005,81.06 ; U54_UB1.6@113.413,81.06 112.005,81.06
  Top Layer w0.381: 96.545,70.079 96.577,70.047 RN14_UB1.5@96.577,68.25 ; 97.333,70.079 97.377,70.034 RN14_UB1.3@97.377,68.25 ; 98.146,70.079 98.177,70.047 RN14_UB1.1@98.177,68.25 ; RN13_UB1.7@100.197,68.25 100.197,70.021 100.254,70.079 ; RN18_UB1.7@100.73,90.399 100.73,91.774 100.838,91.882 100.914,91.882 ; RN13_UB1.5@100.997,68.25 100.997,70.009 101.067,70.079 ; RN18_UB1.5@101.53,90.399 101.53,91.882 ; RN13_UB1.3@101.797,68.25 101.797,69.945 101.93,70.079 ; RN18_UB1.3@102.33,90.399 102.33,91.882 102.33,91.948 ; RN13_UB1.1@102.597,68.25 102.597,70.009 102.667,70.079 ; RN18_UB1.1@103.13,90.399 103.13,91.882 103.13,92.05 ; RN11_UB1.7@104.616,68.25 104.616,69.996 104.699,70.079 ; RN16_UB1.7@105.277,90.348 105.277,91.882 ; 105.308,70.079 105.416,69.971 RN11_UB1.5@105.416,68.25 ; RN16_UB1.5@106.077,90.348 106.077,91.882 ; RN11_UB1.3@106.216,68.25 106.216,69.729 106.566,70.079 ; RN16_UB1.3@106.877,90.348 106.877,91.882 ; RN16_UB1.1@107.677,90.348 107.677,91.882 ; RN15_UB1.7@109.823,90.297 109.823,91.882 ; RN15_UB1.5@110.623,90.297 110.623,91.882 ; RN15_UB1.3@111.423,90.297 111.423,91.882 ; RN15_UB1.1@112.224,90.297 112.224,91.865
  Top Layer w0.762: C405_UB1.2@63.017,92.939 C405_UB1.2@63.043,92.939 v3@64.033,92.939 ; R229_UB1.1@73.279,41.783 73.431,41.631 D21_UB1.1@74.905,41.631 ; RN14_UB1.7@95.656,68.097 95.656,70.079 96.545,70.079 97.333,70.079 98.146,70.079 100.254,70.079 101.067,70.079 101.93,70.079 102.667,70.079 104.699,70.079 105.308,70.079 106.566,70.079 ; 100.914,91.882 101.53,91.882 102.33,91.882 103.13,91.882 105.277,91.882 106.077,91.882 106.877,91.882 107.677,91.882 109.823,91.882 110.623,91.882 111.423,91.882 111.989,91.882 ; 106.642,70.079 107.188,70.079 107.213,70.053 107.213,69.367 ; 107.213,69.367 108.585,67.996 108.585,64.719 v2(108.128,64.719) 108.153,64.745 108.153,68.123 107.213,68.123 107.213,69.367
  Top Layer w1.27: v3(64.592,92.913) v3@64.668,92.989 ; L3_UB1.1@68.732,36.957 L3_UB1.1@69.164,36.957 ; C416_UB1.1@71.044,45.237 71.044,43.358 C255_UB1.1@71.222,43.18 ; v3@71.603,36.982 v3@71.628,36.957 ; R239_UB1.2@73.863,36.957 v3@71.628,36.957 ; C294_UB1.1@81.94,17.399 81.991,17.45 C17_UB1.1@81.991,14.427 ; 82.702,21.234 83.668,22.2 ; R263_UB1.1@83.668,21.26 83.668,22.2 ; U46_UB1.2@83.668,23.647 83.668,22.2 ; L3_UB1.1@69.164,36.957 v3(69.037,36.83) 71.501,36.83 v3@71.628,36.957 ; L3_UB1.1@69.164,36.957 v3@71.628,36.957
  Top Layer w1.524: v3(79.553,20.828) 79.959,21.234 C295_UB1.2@81.661,21.234 82.702,21.234 R263_UB1.1@83.642,21.234
  Top Layer w2.032: v3(79.553,20.828) 79.553,18.136 80.213,17.475 C294_UB1.1@82.017,17.475 82.017,14.453 C17_UB1.1@81.991,14.427
  Mid-Layer 2 w2.032: P2_UB1.1@30.836,86.766 33.503,86.766 34.188,86.081 34.188,77.953 32.385,76.149 32.385,72.187 31.496,71.298 31.496,66.904 34.747,63.652 34.747,57.556 34.874,57.429 ; 34.925,58.725 34.874,58.674 34.874,57.429 ; v3(69.037,36.83) 72.415,36.83 73.33,35.916 73.33,32.741 73.99,32.08 76.302,32.08 77.038,31.344 77.038,23.241 v3@79.477,20.803 ; v3(71.145,36.881) 69.24,36.881 64.668,41.453 56.413,41.453 51.74,46.126 37.084,46.126 34.874,48.336 34.874,57.429
  Mid-Layer 4 w0.381: v1(111.836,81.839) 112.928,81.839 113.233,81.534
  Mid-Layer 4 w1.524: 108.001,58.115 107.95,58.166 107.95,71.958 108.306,72.314 110.098,72.314 111.919,74.136 111.919,76.41 112.166,76.657 112.166,76.81 113.233,77.876 113.233,81.534 114.656,82.956 114.656,85.547 108.763,91.44
  Mid-Layer 4 w2.032: P2_UB1.1@30.836,86.766 34.086,86.766 38.837,91.516 43.459,91.516 45.288,93.345 ; 45.695,98.146 45.695,93.751 45.288,93.345 ; 63.221,92.634 63.119,92.532 ; v3@64.211,92.532 63.119,92.532 ; v3(69.037,36.83) 72.339,36.83 73.254,37.744 80.62,37.744 81.89,39.014 81.89,42.824 82.982,43.917 86.03,43.917 87.224,42.723 91.288,42.723 92.075,43.51 100.736,43.51 104.419,47.193 106.604,47.193 108.001,48.59 108.001,58.115 ; 45.288,93.345 60.554,93.345 61.366,92.532 63.119,92.532
  Bottom Layer w0.381: C368_UB1.2@114.173,81.864 114.148,81.839 v1(111.836,81.839) 111.595,82.08 111.593,82.08 111.214,82.46 111.214,82.461 111.074,82.601 111.073,82.601 ; 111.073,82.601 109.22,82.601 108.864,82.956 110.717,82.956 111.073,82.601
  Bottom Layer w0.762: U35_UB1.8@45.37,108.636 45.37,100.731 C228_UB1.1@45.796,100.305 ; C415_UB1.1@92.126,27.788 92.202,27.711 U61_UB1.8@95.001,27.711 ; v2(99.314,70.053) 99.517,69.85 R40_UB1.1@99.517,66.345 ; R39_UB1.1@105.283,88.494 105.283,91.262 105.893,91.872 v2(108.763,91.872) ; v2(106.858,59.919) 107.721,59.919 108.102,60.3 108.102,63.881 C265_UB1.1@108.128,63.906 v2(108.128,64.719)
  Bottom Layer w1.27: v2@45.466,98.73 C228_UB1.1@45.466,100.305 ; v3(79.553,20.828) 82.423,20.828 89.383,27.788 C415_UB1.1@92.126,27.788
  other v2: 94.158,42.977 91.923,43.002 91.923,44.145 94.158,44.145 45.456,98.703
+5V_UB2: C17_UB2.1 C228_UB2.1 C237_UB2.2 C238_UB2.2 C254_UB2.1 C255_UB2.1 C258_UB2.1 C265_UB2.1 C266_UB2.2 C294_UB2.1 C295_UB2.2 C367_UB2.1 C368_UB2.2 C405_UB2.2 C415_UB2.1 C416_UB2.1 D21_UB2.1 L3_UB2.1 P2_UB2.1 R39_UB2.1 R40_UB2.1 R229_UB2.1 R239_UB2.2 R263_UB2.1 R283_UB2.2 RN11_UB2.1 RN11_UB2.3 RN11_UB2.5 RN11_UB2.7 RN13_UB2.1 RN13_UB2.3 RN13_UB2.5 RN13_UB2.7 RN14_UB2.1 RN14_UB2.3 RN14_UB2.5 RN14_UB2.7 RN15_UB2.1 RN15_UB2.3 RN15_UB2.5 RN15_UB2.7 RN16_UB2.1 RN16_UB2.3 RN16_UB2.5 RN16_UB2.7 RN18_UB2.1 RN18_UB2.3 RN18_UB2.5 RN18_UB2.7 U35_UB2.8 U42_UB2.6 U46_UB2.2 U54_UB2.6 U58_UB2.1 U61_UB2.8 | length 543
  Top Layer w0.254: v1(160.02,79.527) 160.02,79.657 160.093,79.73 160.093,79.352 160.372,79.073 U54_UB2.6@161.442,79.073 ; v1@160.401,57.734 161.011,57.734 161.345,57.4 U42_UB2.6@162.334,57.4 ; v1(215.138,97.13) 215.163,97.13 215.719,96.574 U58_UB2.1@215.719,94.64
  Top Layer w0.381: v1(146.939,59.4) 146.939,60.451 ; 147.193,63.754 146.939,63.5 146.939,62.713 ; RN14_UB2.7@148.082,60.319 147.071,60.319 146.939,60.451 ; RN14_UB2.5@148.082,61.119 146.958,61.119 146.939,61.138 ; RN14_UB2.3@148.082,61.919 146.971,61.919 146.939,61.951 ; RN14_UB2.1@148.082,62.719 146.945,62.719 146.939,62.713 ; 150.089,90.601 150.095,90.595 RN18_UB2.5@150.095,89.052 ; RN18_UB2.3@150.895,89.052 150.895,90.595 150.901,90.601 ; 151.587,90.601 151.695,90.493 RN18_UB2.1@151.695,89.052 ; 153.518,90.601 153.704,90.415 RN16_UB2.7@153.704,89.027 ; RN13_UB2.7@153.859,67.158 153.859,68.608 153.932,68.682 ; 154.457,90.601 154.504,90.555 RN16_UB2.5@154.504,89.027 ; RN13_UB2.5@154.659,67.158 154.659,68.553 154.788,68.682 ; 155.245,90.601 155.304,90.542 RN16_UB2.3@155.304,89.027 ; RN13_UB2.3@155.459,67.158 155.459,68.515 155.626,68.682 ; 156.032,90.601 156.104,90.53 RN16_UB2.1@156.104,89.027 ; RN13_UB2.1@156.259,67.158 156.259,68.68 156.261,68.682 ; 158.093,90.601 158.064,90.601 158.21,90.455 RN15_UB2.7@158.21,89.027 ; RN11_UB2.7@158.38,67.158 158.38,68.515 158.547,68.682 ; 158.826,90.601 159.01,90.417 RN15_UB2.5@159.01,89.027 ; RN11_UB2.5@159.18,67.158 159.18,68.579 159.283,68.682 ; 159.664,90.601 159.639,90.601 159.81,90.43 RN15_UB2.3@159.81,89.027 ; 159.969,68.682 159.98,68.67 RN11_UB2.3@159.98,67.158 ; 146.939,60.451 146.939,61.138 ; 146.939,61.138 146.939,61.951 ; 146.939,61.951 146.939,62.713
  Top Layer w0.762: 146.939,63.5 146.939,63.754 147.193,63.754 151.486,63.754 151.841,64.11 C265_UB2.1@151.841,66.711 151.841,68.377 152.146,68.682 153.932,68.682 154.788,68.682 155.626,68.682 156.261,68.682 158.547,68.682 159.283,68.682 159.969,68.682 160.781,68.682 v2@160.781,68.68 ; 149.098,88.906 149.098,90.373 149.327,90.601 150.089,90.601 150.901,90.601 151.587,90.601 152.806,90.601 ; v1@152.806,86.382 152.806,90.601 ; 158.064,90.601 156.032,90.601 155.245,90.601 154.457,90.601 153.518,90.601 152.806,90.601 ; 158.093,90.601 158.826,90.601 159.639,90.601 160.579,90.601 ; 159.664,90.601 160.579,90.601 ; 160.807,88.9 160.807,90.373 160.579,90.601 ; RN11_UB2.1@160.96,67.159 v2@160.96,68.682 ; v2(167.005,88.875) 165.278,90.601 160.579,90.601 ; C258_UB2.1@189.382,36.373 R239_UB2.2@189.382,37.973 189.382,39.649 189.484,39.548 D21_UB2.1@190.932,39.548
  Top Layer w1.27: v3(168.351,20.599) 168.351,19.863 168.834,19.38 174.676,19.38 ; v3(175.057,17.78) v3@175.057,17.831 ; U46_UB2.2@175.793,23.266 175.793,20.498 ; C17_UB2.1@177.444,14.63 177.521,14.707 177.521,17.755 176.327,17.755 ; 174.676,19.38 175.793,20.498 ; 174.676,19.38 174.981,19.38 175.057,19.304 v3@175.057,17.831 ; v3@175.057,17.831 175.006,17.78 175.031,17.755 176.327,17.755 ; 175.793,20.498 175.793,18.288 176.327,17.755
  Top Layer w2.032: 173.457,48.666 v4@174.523,48.666
  Mid-Layer 3 w0.762: v2(160.985,68.656) 160.985,63.449 v1(161.544,62.89)
  Mid-Layer 3 w1.016: v3(205.537,97.561) 207.747,97.561 208.458,98.273 213.995,98.273 v1(215.138,97.13)
  Mid-Layer 3 w1.27: 160.985,57.937 164.846,57.937
  Mid-Layer 3 w1.524: v1(161.544,62.89) 163.551,62.89 165.303,61.138 ; 164.846,57.937 165.303,58.395 165.303,59.969 ; 181,60.706 180.848,60.554 165.887,60.554 ; 187.376,43.155 187.401,43.129 v3(188.925,43.129) ; 165.303,59.969 165.303,61.138 ; 165.303,59.969 165.887,60.554 ; 165.303,61.138 165.887,60.554
  Mid-Layer 3 w2.032: 160.731,79.959 162.001,79.959 164.109,82.067 168.046,82.067 169.24,83.261 ; 167.411,88.443 169.24,86.614 ; v4(174.955,48.768) 175.362,48.768 177.775,46.355 182.55,46.355 182.702,46.203 ; v3(175.057,17.78) 175.108,17.729 178.74,17.729 180.848,19.837 180.848,27.661 182.448,29.261 187.35,29.261 188.849,30.759 v3(188.849,40.03) ; v4@175.565,48.616 177.267,48.616 ; 177.927,46.203 182.702,46.203 ; 187.376,43.155 185.623,43.155 ; 187.401,43.129 187.401,40.335 187.706,40.03 ; 188.671,42.291 188.671,40.208 v3(188.849,40.03) ; 192.126,42.545 188.874,42.545 188.824,42.494 188.849,42.469 v3(188.849,40.03) ; 207.315,46.203 204.851,46.203 199.161,40.513 190.119,40.513 189.992,40.64 189.382,40.03 v3(188.849,40.03) ; 169.24,83.261 170.917,84.938 ; 169.24,83.261 169.24,86.614 ; 169.24,86.614 170.917,84.938 ; 170.917,84.938 178.918,84.938 ; 177.267,48.616 178.359,47.523 181,47.523 ; 177.267,48.616 180.746,48.616 181,48.87 ; 178.918,84.938 181,84.938 181,82.855 ; 178.918,84.938 181,82.855 ; 181,47.523 183.159,47.523 184.556,46.126 ; 181,47.523 181,48.87 ; 181,48.87 181,60.706 181,82.855 ; 182.702,46.203 184.556,44.348 ; 184.556,44.221 185.623,43.155 ; 184.556,44.221 184.556,41.326 185.623,40.259 ; 184.556,44.221 184.556,44.348 ; 184.556,44.348 184.556,46.126 ; 184.556,46.126 185.623,45.06 185.623,43.155 ; 185.623,40.259 185.852,40.03 187.706,40.03 ; 185.623,40.259 185.623,43.155 ; 187.706,40.03 v3(188.849,40.03)
  Mid-Layer 3 w2.54: 192.126,42.545 198.831,42.545 202.489,46.203 204.851,46.203 219.024,46.203 ; v3(205.537,97.561) 205.435,97.46 205.435,92.329 206.781,90.983 208.005,90.983 208.106,90.881 213.686,90.881 217.725,86.843 218.034,86.843 223.469,81.407 ; P2_UB2.1@230.149,81.458 230.149,78.537 229.133,77.521 226.619,77.521 225.095,75.997 ; 219.024,46.203 222.606,46.203 225.4,48.997 225.4,66.14 225.095,66.445 225.095,75.997 ; 219.024,46.203 223.469,50.648 223.469,81.407 ; 223.469,81.407 225.095,79.781 225.095,75.997
  Bottom Layer w0.508: C238_UB2.2@158.496,78.816 158.496,79.502 ; C228_UB2.1@158.496,80.772 158.496,79.502 ; v1(160.401,57.887) 159.817,58.471 C237_UB2.2@159.817,59.284 159.817,61.163 v1(161.544,62.89) C367_UB2.1@161.544,64.237 ; C405_UB2.2@161.239,79.737 160.23,79.737 v1(160.02,79.527) 159.995,79.502 158.496,79.502
  Bottom Layer w0.762: v2(151.638,63.805) 151.638,64.287 151.968,64.618 R40_UB2.1@153.619,64.618 ; v1(152.806,86.309) 153.111,86.004 R39_UB2.1@153.111,85.065 ; U61_UB2.8@161.609,21.057 166.167,21.057 166.663,20.56 C416_UB2.1@166.663,20.117 ; C368_UB2.2@214.655,94.336 214.655,95.174 214.63,95.199 214.351,95.199 214.173,95.377 214.173,96.672 214.63,97.13 v1(215.138,97.13)
  Bottom Layer w1.016: v3(205.537,97.561) 205.562,97.536 207.162,97.536 208.61,98.984 211.76,98.984 213.233,100.457 213.233,104.013 212.522,104.724 ; 212.522,105.715 212.522,104.724 ; U35_UB2.8@212.522,109.093 212.522,104.724
  Bottom Layer w2.032: C415_UB2.1@164.733,21.768 166.954,21.768 167.437,21.285 167.437,20.955 167.259,20.777 167.437,20.599 v3(168.351,20.599)
  other v2: 152.552,68.63
+5VA_UB1: C242_UB1.1 C284_UB1.1 C285_UB1.2 C311_UB1.1 C312_UB1.1 C327_UB1.1 C328_UB1.1 C373_UB1.1 C374_UB1.2 C393_UB1.1 C395_UB1.1 D27.1 P3_UB1.11 P3_UB1.26 P4_UB1.2 R203_UB1.1 R219_UB1.2 R229_UB1.2 R283_UB1.1 U42_UB1.43 U48_UB1.8 U49_UB1.8 U50_UB1.8 U54_UB1.43 U56_UB1.3 U57_UB1.4 | length 372
  Top Layer w0.254: R219_UB1.2@101.295,48.73 C242_UB1.1@101.295,50.216 ; R203_UB1.1@102.985,48.73 R203_UB1.1@103.099,48.616 ; U42_UB1.43@104.049,54.785 104.049,56.271 v1(104.064,56.286) ; v1(108.966,78.334) 109.063,78.236 U54_UB1.43@109.063,76.71
  Top Layer w0.762: C312_UB1.1@68.605,97.333 68.656,97.282 U50_UB1.8@71.303,97.282 v1(72.72,97.282) ; R219_UB1.2@101.308,48.641 R203_UB1.1@102.997,48.641 ; C395_UB1.1@115.895,68.758 117.627,68.758 117.978,68.408 C393_UB1.1@117.978,67.843
  Top Layer w1.016: P3_UB1.26@64.376,129.952 64.376,129.444 63.424,128.492 P3_UB1.11@63.424,128.047 63.424,127.584 65.481,125.527 66.777,125.527 69.139,123.165 69.139,120.345 70.002,119.482 U49_UB1.8@71.315,119.482 v2(72.72,119.482) ; v3(68.605,94.996) C312_UB1.1@68.605,97.333 ; U48_UB1.8@71.278,108.382 v2(72.72,108.382) ; v2@105.664,72.761 105.7,72.796 C373_UB1.1@106.629,72.796 ; U56_UB1.3@116.073,60.808 117.551,60.808 v2(117.577,60.833) ; U57_UB1.4@116.276,42.469 117.952,42.469 v1(117.978,42.443) ; C393_UB1.1@117.978,67.843 117.978,67.544 118.328,67.894 v2(118.872,67.894)
  Top Layer w1.27: P4_UB1.2@100.533,95.853 102.838,95.853 105.258,98.273 D27.1@106.07,98.273
  Top Layer w1.524: R229_UB1.2@73.127,43.409 73.127,44.755 73.381,45.009 v3@74.676,45.009
  Mid-Layer 2 w0.254: v1(104.064,56.286) v1@104.064,56.337
  Mid-Layer 2 w1.016: v2(105.537,72.878) 105.537,70.968 107.01,69.494 111.125,69.494 114.122,66.497 118.872,66.497 ; v2(117.577,60.833) 118.252,60.833 118.872,61.453 118.872,66.497 ; v1(117.978,42.443) 114.452,42.443 108.966,47.93 100.787,47.93 98.146,50.571 95.199,50.571 94.147,49.519 v2(94.147,46.914) ; v2(118.872,67.894) 118.872,66.497 ; v2(94.147,46.914) v2(91.923,46.914) 91.948,46.888 v2(91.948,45.339) 91.973,45.364 v2(94.183,45.364) 94.147,45.401 v2(94.147,46.914)
  Mid-Layer 4 w0.762: v1(72.72,97.282) 73.101,97.282 73.838,98.019
  Mid-Layer 4 w1.016: 64.643,131.877 64.376,131.61 P3_UB1.26@64.376,129.952 64.376,129.324 63.424,128.372 P3_UB1.11@63.424,128.047 63.424,127.61 65.329,125.705 67.589,125.705 ; v2(72.72,108.382) 73.762,108.382 73.838,108.458 ; 104.648,76.479 108.051,76.479 108.966,77.394 v1(108.966,78.334)
  Mid-Layer 4 w1.27: P4_UB1.2@100.533,95.853 103.08,95.853 103.149,95.783
  Mid-Layer 4 w1.524: 64.643,131.877 64.948,132.182 73,132.182 73.558,131.623 73.558,127.381 72.492,126.314 72.492,124.13 ; 94.513,50.749 94.564,50.698 101.321,50.698 ; 101.321,49.86 101.321,50.698 ; v1(104.064,56.286) 104.064,52.578 102.184,50.698 101.321,50.698
  Mid-Layer 4 w2.032: 67.589,125.705 70.917,125.705 72.492,124.13 72.492,120.269 73.838,118.923 73.838,108.458 73.838,98.019 73.838,94.615 73.685,94.463 ; v3@68.605,94.894 v3(68.605,94.996) ; v3(74.727,45.034) 74.955,45.034 76.708,45.034 ; 76.708,46.787 77.14,47.219 78.892,47.219 ; 103.149,95.783 103.2,95.783 103.581,95.402 103.581,79.604 104.648,78.537 104.648,76.479 104.648,69.215 103.403,67.97 100.508,67.97 94.513,61.976 94.513,50.749 93.802,50.038 ; 76.708,45.034 78.257,45.034 ; 76.708,45.034 78.892,47.219 ; 78.257,45.034 79.832,45.034 82.017,47.219 ; 78.257,45.034 80.442,47.219 ; 78.892,47.219 80.442,47.219 ; 80.442,47.219 82.017,47.219 ; 82.017,47.219 87.884,47.219 ; 87.884,47.219 90.983,47.219 ; 87.884,47.219 89.205,45.898 93.751,45.898 93.802,45.949 93.802,47.32 ; 90.983,47.219 93.802,50.038 ; 90.983,47.219 93.701,47.219 93.802,47.32 ; 93.802,47.32 93.802,50.038
  Mid-Layer 4 w2.54: v3(68.605,94.996) 69.139,94.463 73.685,94.463 81.788,94.463 82.88,95.555 89.002,95.555 ; v3@74.955,45.034 76.708,46.787 ; 98.527,86.69 97.866,86.69 93.853,90.703 ; 102.311,90.703 97.053,90.703 ; 89.002,95.555 92.202,95.555 ; 89.002,95.555 93.853,90.703 ; 92.202,95.555 94.539,95.555 97.053,93.04 97.053,90.703 ; 92.202,95.555 97.053,90.703 ; 93.853,90.703 97.053,90.703
  Bottom Layer w0.254: C285_UB1.2@103.429,56.896 103.454,56.896 v1(104.064,56.286) ; C374_UB1.2@108.229,78.638 108.661,78.638 v1(108.966,78.334)
  Bottom Layer w0.508: C284_UB1.1@104.013,54.331 104.013,56.236 v1(104.064,56.286)
  Bottom Layer w1.016: v2(72.72,108.382) C328_UB1.1@74.27,108.382 C327_UB1.1@75.783,108.382 ; v2(72.72,119.482) C311_UB1.1@74.651,119.482
  other v1: 101.27,49.428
